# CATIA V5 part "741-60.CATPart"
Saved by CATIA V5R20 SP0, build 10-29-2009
Part number: 741-60
Bounding box of the stored display mesh (mm): x -47.5 to 47.5, y -47.5 to 47.5, z -60 to 56
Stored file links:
  C:\Users\Utente\Desktop\IO LAVORO\3D X SITO CF\X SITO\741\741-60.CATPart
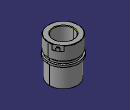
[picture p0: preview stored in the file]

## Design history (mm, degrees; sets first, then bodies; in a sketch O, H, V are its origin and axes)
Set1
  DatumSurface1 to DatumSurface42 "741-60"
Body1 (main body)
